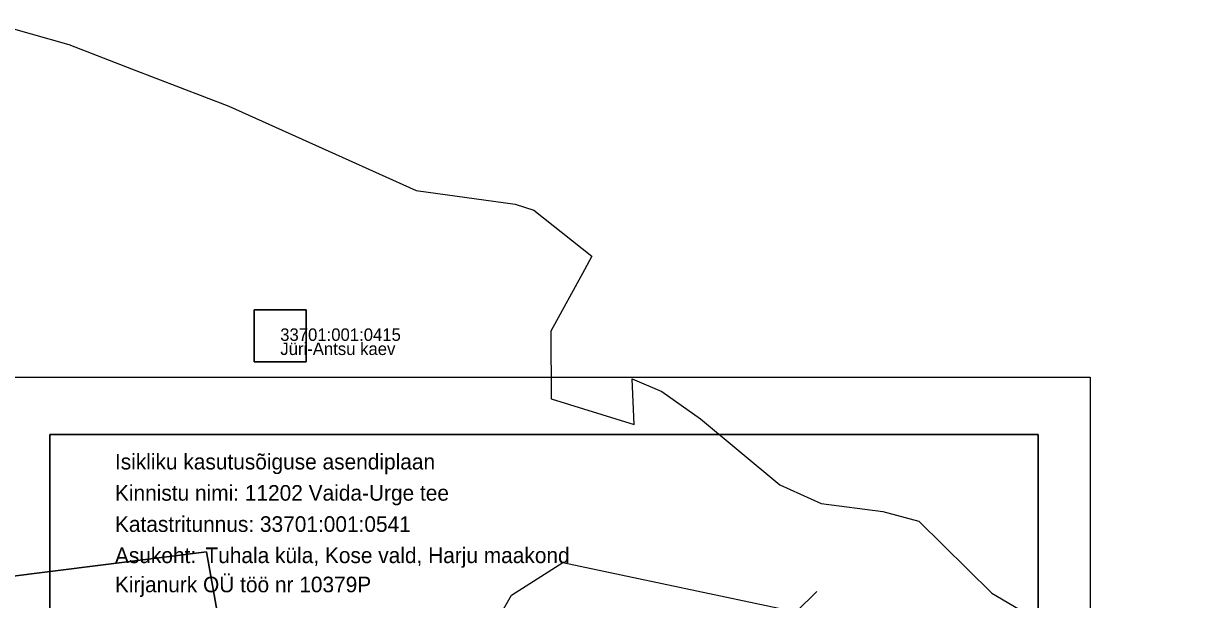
# Model space of a CAD drawing. Extents: x 554947 to 555436, y 6564938 to 6565792.
# Drawn here: x 555187.9 to 555410.9, y 6565659 to 6565769.8 of the extents above; entities that cross this region are included whole.
import ezdxf

# ---------------------------------------------------------------- set-up
doc = ezdxf.new("R2010")
doc.units = 0
for name, color, linetype in [('PIIR', 7, 'Continuous'), ('PR_SIDE', 7, 'Continuous'), ('VORMISTUS_3', 7, 'Continuous')]:
    doc.layers.add(name, color=color, linetype=linetype)

msp = doc.modelspace()

# ---------------------------------------------------------------- linework, layer by layer
at = {"layer": 'PIIR'}
for points in [[(555182.13, 6565769.81), (555196.73, 6565765.71), (555208.77, 6565761.06), (555227.5, 6565753.84), (555249.25, 6565744.03), (555263.48, 6565737.62), (555282.51, 6565735.04), (555286.12, 6565733.88), (555297.3, 6565725), (555295.86, 6565722.37), (555289.37, 6565710.58), (555289.43, 6565697.6), (555305.41, 6565692.68), (555305.05, 6565701.45), (555310.71, 6565699.01), (555318.19, 6565693.78), (555333.39, 6565681.05), (555341.38, 6565677.46), (555353.22, 6565675.94), (555360.12, 6565674.06), (555374.15, 6565660.24), (555410.9, 6565638.65)], [(555234.35, 6565605.6), (555223.17, 6565668.21), (555183.94, 6565663.24)]]:
    msp.add_lwpolyline(points, dxfattribs=at)
for points in [[(555232.36, 6565714.73), (555232.34, 6565704.73), (555242.34, 6565704.71), (555242.36, 6565714.71)], [(555232.36, 6565714.73), (555242.36, 6565714.71), (555242.34, 6565704.71), (555232.34, 6565704.73)], [(555193.24, 6565604.68), (555183.94, 6565663.24), (555223.17, 6565668.21), (555234.35, 6565605.6), (555225.47, 6565605.89), (555193.7, 6565602.7)]]:
    msp.add_lwpolyline(points, close=True, dxfattribs=at)
at = {"layer": 'PR_SIDE'}
msp.add_lwpolyline([(555232.4, 6565605.17), (555232.48, 6565605.3), (555234.36, 6565605.15), (555239.41, 6565608.98), (555257.15, 6565616.75), (555281.8, 6565659.83), (555291.68, 6565666.13), (555336.53, 6565656.68), (555340.55, 6565660.53)], dxfattribs=at)
at = {"layer": 'VORMISTUS_3'}
for points in [[(555183.07, 6565701.75), (555393.07, 6565701.75), (555393.07, 6565404.75), (555183.07, 6565404.75)], [(555193.07, 6565415.75), (555383.07, 6565415.75), (555383.07, 6565690.75), (555193.07, 6565690.75)], [(555193.07, 6565690.75), (555383.07, 6565690.75), (555383.07, 6565415.75), (555193.07, 6565415.75)]]:
    msp.add_lwpolyline(points, close=True, dxfattribs=at)

# ---------------------------------------------------------------- texts
at = {"layer": 'PIIR'}
for s, p in [('33701:001:0415', (555237.35, 6565708.74)), ('Jüri-Antsu kaev', (555237.38, 6565706.02))]:
    msp.add_text(s, height=2.4, dxfattribs=at).set_placement(p)
at = {"layer": 'VORMISTUS_3'}
for s, p in [('Isikliku kasutusõiguse asendiplaan', (555205.58, 6565684.02)), ('Kinnistu nimi: 11202 Vaida-Urge tee', (555205.58, 6565678.02)), ('Katastritunnus: 33701:001:0541', (555205.58, 6565672.02)), ('Asukoht: ', (555205.58, 6565666.02)), ('Tuhala küla, Kose vald, Harju maakond', (555222.98, 6565666.02))]:
    msp.add_text(s, height=3, dxfattribs=at).set_placement(p)
msp.add_text('Kirjanurk OÜ töö nr 10379P', height=3, rotation=360, dxfattribs=at).set_placement((555205.57, 6565660.41))

doc.saveas('drawing.dxf')
